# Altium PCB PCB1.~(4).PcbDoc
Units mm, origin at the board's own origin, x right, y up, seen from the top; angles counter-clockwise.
Board outline 0.45 x 30.25 mm, 2 copper layers (Top Layer, Bottom Layer); 14 components, 11 nets, 42 pads, 2 vias.
Unrouted connection lines stored in the file: 24.
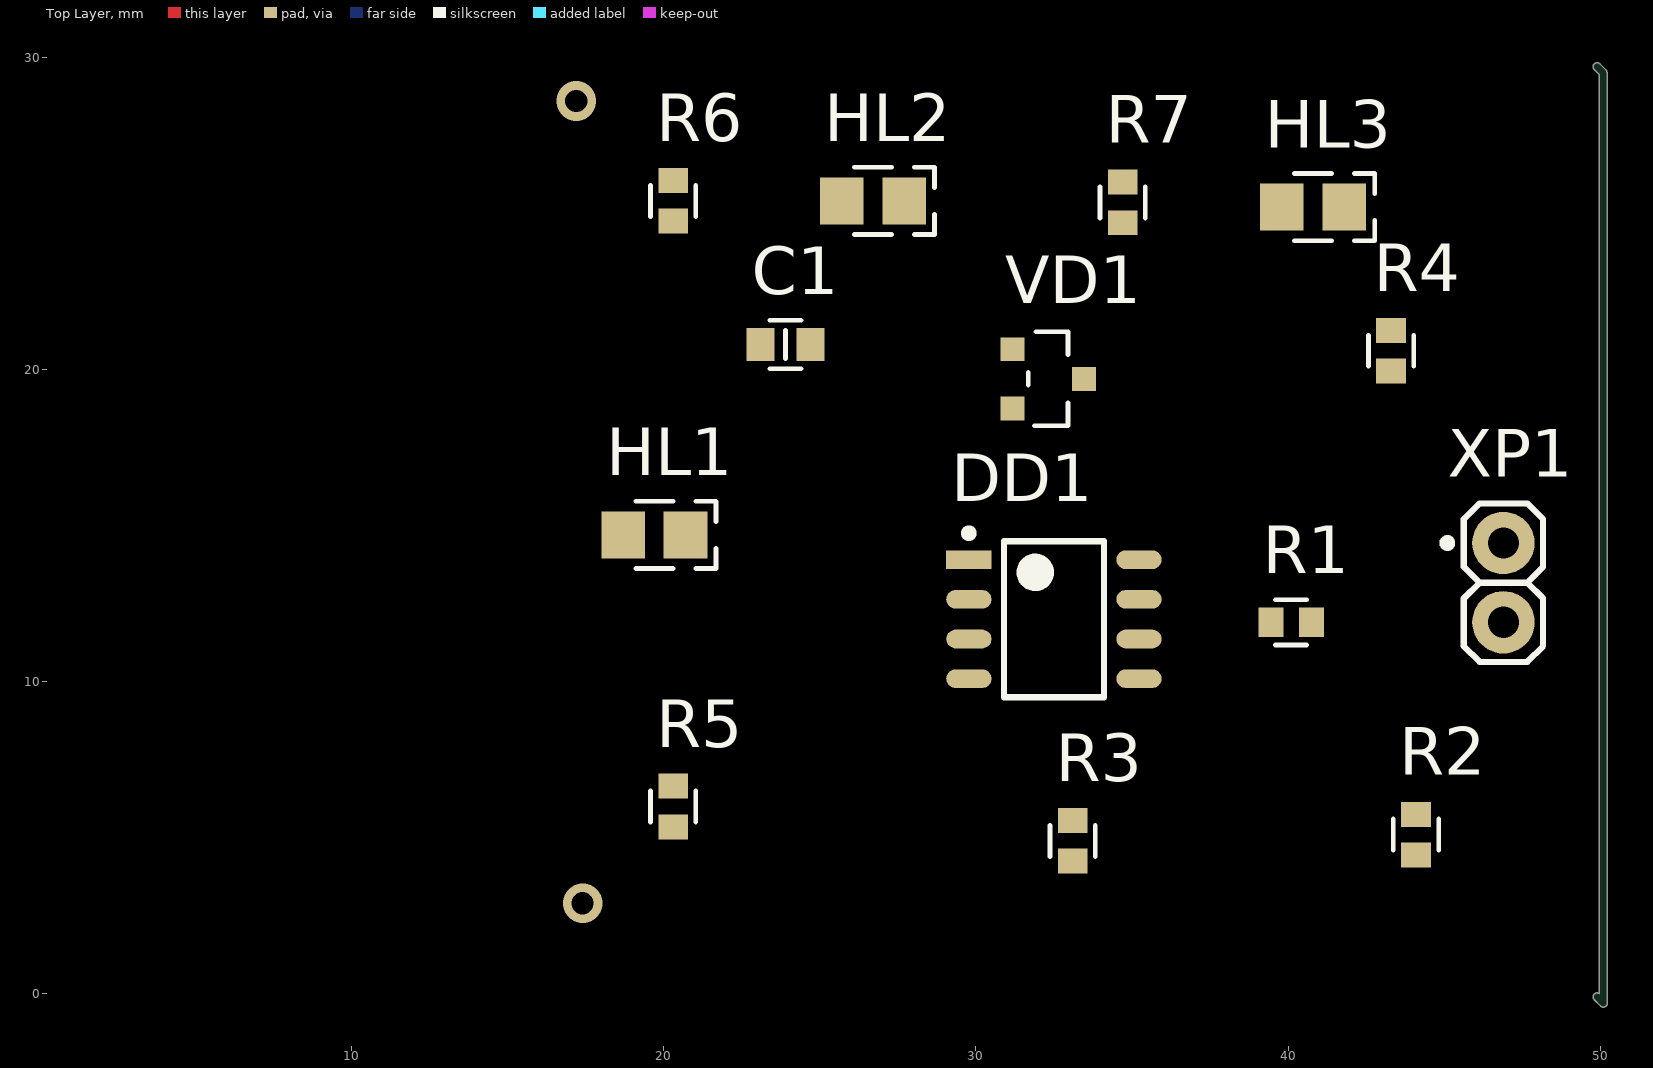
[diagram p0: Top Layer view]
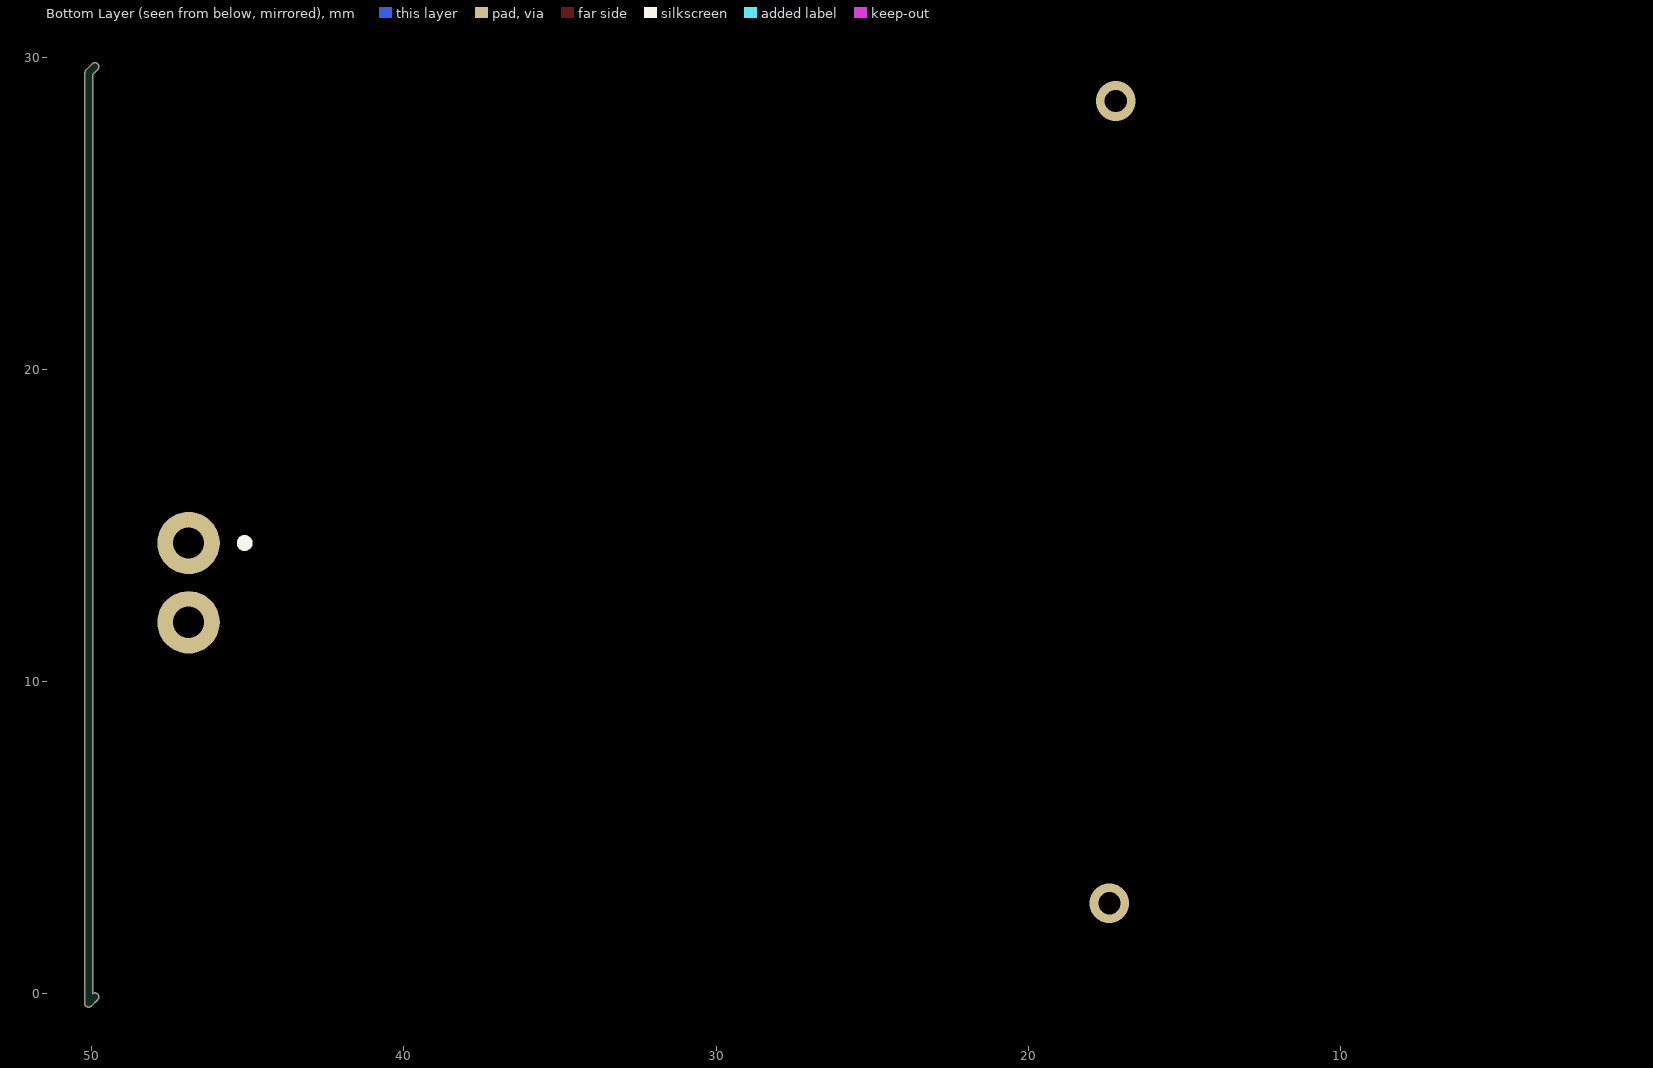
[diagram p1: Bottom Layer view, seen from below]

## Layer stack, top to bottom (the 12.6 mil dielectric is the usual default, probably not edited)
Top Solder: solder mask 0.0102, Solder Resist, Dk 3.5
Top Layer: signal copper 0.0356
Dielectric 1: dielectric 0.32, FR-4, Dk 4.8
Bottom Layer: signal copper 0.0356
Bottom Solder: solder mask 0.0102, Solder Resist, Dk 3.5

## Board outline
49.81,-0.19 cw(c49.9,-0.1) 49.973,0.005 49.973,29.447 49.81,29.61 cw(c49.9,29.7) 49.99,29.79 50.19,29.59 50.227,29.5 50.227,-0.3 cw(c50.1,-0.3) 50.009,-0.39 50.01,-0.39

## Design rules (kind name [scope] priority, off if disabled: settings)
Clearance [All] p1: gap=0.254 ignorepadtopadclearanceinfootprint=FALSE
PolygonConnect [All] p1: connectstyle=Relief reliefconductorwidth=0.254 reliefentries=4 polygonreliefangle="90 Angle" airgapwidth=0.254
RoutingVias [All] p1: holewidth=0.711 width=1.27 viastyle="Through Hole" minholewidth=0.711 minwidth=1.27 maxholewidth=0.711 maxwidth=1.27
SolderMaskExpansion [All] p1: expansion=0.102 istentingtop=FALSE
Width [All] p1: maxlimit=0.254 minlimit=0.254 preferedwidth=0.254
30 further rules are at their usual default settings.

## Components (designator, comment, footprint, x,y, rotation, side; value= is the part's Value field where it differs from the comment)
C1 "Capacitor" 0603C 23.9,20.8 r0 top value="0,1 мк"
DD1 "LM393" SOIC-8 32.5,12 r0 top
HL1 "LED" 0805D 19.7,14.7 r0 top
HL2 "LED" 0805D 26.7,25.4 r0 top
HL3 "LED" 0805D 40.8,25.2 r0 top
R1 "Resistor" 0603R 40.1,11.9 r0 top value=10
R2 "Resistor" 0603R 44.1,5.1 r90 top value=4,3
R3 "Resistor" 0603R 33.1,4.9 r90 top value="43 к"
R4 "Resistor" 0603R 43.3,20.6 r90 top value=4,3
R5 "Resistor" 0603R 20.3,6 r90 top value="10 к"
R6 "Resistor" 0603R 20.3,25.4 r90 top value="10 к"
R7 "Resistor" 0603R 34.7,25.35 r90 top value="10 к"
VD1 "BZX84-B11" SOT23-3 32.3,19.7 r0 top value="11 В"
XP1 "PLS-2" PLS2 46.9,14.44 r0 top

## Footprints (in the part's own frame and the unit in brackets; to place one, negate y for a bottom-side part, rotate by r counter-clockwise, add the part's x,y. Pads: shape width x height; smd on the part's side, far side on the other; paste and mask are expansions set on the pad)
0603C [mm] "Chip Resistor, 2-Leads, Body 1,40x0,80mm, IPC Medium Density"
  rect 0.9x1.05 smd: 1(-0.8,0) 2(0.8,0)
  silkscreen extent -0.5,-0.77 0.5,0.77, body extent -0.85,-0.45 0.85,0.45, height 0.9
0603R [mm] "Chip Resistor, 2-Leads, Body 1.60x0.85mm, IPC Medium Density"
  rect 0.8x0.95 smd: 1(-0.65,0) 2(0.65,0)
  silkscreen extent -0.5,-0.72 0.5,0.72, body extent -0.87,-0.47 0.88,0.48, height 0.9
0805D [mm]
  rect 1.4x1.5 smd: 1(-1,0) 2(1,0)
  silkscreen extent -0.6,-1.07 1.97,1.07, body extent -1.07,-0.7 1.07,0.7, height 0.7
PLS2 [mm]
  round 2 hole 1: 1(0,0) 2(0,-2.54)
  silkscreen extent -1.92,-3.81 1.27,1.27, body extent -1.27,-3.81 1.27,1.27, height 8.44
SOIC-8 [mm] "for operational amplifier"
  rect 1.45x0.6 smd: 1(-2.725,1.905)
  oval 1.45x0.6 smd: 2(-2.725,0.635) 3(-2.725,-0.635) 4(-2.725,-1.905) 5(2.725,-1.905) 6(2.725,-0.635) 7(2.725,0.635) 8(2.725,1.905)
  silkscreen extent -2.85,-2.5 1.6,2.88, body extent -3,-2.5 3,2.5, height 1.75
SOT23-3 [mil]
  rect 30x30 smd: 1(-44.29,37.4) 2(-44.29,-37.6) 3(45.71,-0.1)
  silkscreen extent -25,-59 26,59, body extent -48,-60 50,59, height 41

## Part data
C1: library part Capacitor_0,1u_10_50V_X7R_0603C, "Конденсатор 0603C ёмкостью 0,1 мк 10%, 50 В, X7R", Capacity (nF)=100, Dielectric=X7R, Tolerance=10%, Voltage (V)=50
DD1: "Двойной маломощный компаратор напряжения", Package="SOIC-8 Texas Instruments"
HL1: "Светодиод", Color=Красный
HL2: "Светодиод", Color=Желтый
HL3: "Светодиод", Color=Зеленый
R1: library part Resistor_10_1_0603, "Резистор номиналом 10 Ом 1%", Tolerance=1%
R2 R4: library part Resistor_4.3_1_0603, "Резистор номиналом 4,3 Ом 1%", Tolerance=1%
R3: library part Resistor_43k_1_0603, "Резистор номиналом 43 кОм 1%", Tolerance=1%
R5 R6 R7: library part Resistor_10k_1_0603, "Резистор номиналом 10 кОм 1%", Tolerance=1%
VD1: "Стабилитрон на 11 В, рассеиваемая мощность 0.25 Вт", Current nominal (mA)=5, Power (W)=0.25, Voltage nominal (V)=11
XP1: "Гребенка 2 пина"

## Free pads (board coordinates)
  rect 0.7x1.3 on Mech1: 3(5.8,17.5) 4(5.3,1.5) 5(2.1,27.6) 6(6.6,23.3) 7(7.4,24.3) 9(5.1,1.4)
  round 2 on Mech1: 8(5.3,1.5)

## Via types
v1: diameter 1.27, hole 0.711, Top Layer to Bottom Layer, 2 vias

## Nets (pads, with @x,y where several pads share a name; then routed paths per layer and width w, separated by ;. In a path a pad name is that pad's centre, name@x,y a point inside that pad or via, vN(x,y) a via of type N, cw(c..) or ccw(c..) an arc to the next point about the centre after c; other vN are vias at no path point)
GND: C1.1 DD1.4 HL3.2 R3.1 VD1.1 VD1.2 XP1.2
NetC1_2: C1.2 DD1.8
NetDD1_1: DD1.1 HL1.2 R6.2
NetDD1_2: DD1.2 DD1.6 R4.1 VD1.3
NetDD1_3: DD1.3 R1.1 R2.2
NetDD1_5: DD1.5 R2.1 R3.2
NetDD1_7: DD1.7 HL2.2 R7.2
NetHL1_1: HL1.1 R5.1
NetHL2_1: HL2.1 R6.1
NetHL3_1: HL3.1 R7.1
NetR1_2: R1.2 R4.2 R5.2 XP1.1
copper on no net:
  other v1: 17.4,2.9 17.2,28.6

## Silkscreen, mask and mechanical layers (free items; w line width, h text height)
Mechanical 1:
  lines w0.254: 16.2,1.2 16.2,6.4 16.2,29.7 49.9,29.7 50.1,29.5 50.1,1.3 50.2,1.2 16.2,1.2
